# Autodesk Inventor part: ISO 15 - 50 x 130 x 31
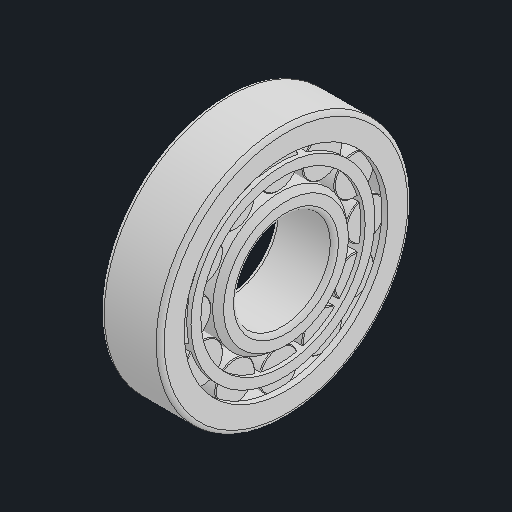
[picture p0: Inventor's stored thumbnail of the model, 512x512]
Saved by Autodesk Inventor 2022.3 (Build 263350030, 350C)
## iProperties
Created: 2020-09
Part Number: ISO 15 - 50 x 130 x 31
Material: Типовые
Document SubType Name: Modeling
Designer: Карташов
Density: 1 g/cm^3
Appearance: По умолчанию
Title: D:\мои документы\Ирина\_WorldSkills\2020_09 ФНЧ\Module A\GIVEN\ISO 15 - 50 x 130 x 31.stp
Author: Дом
Sending System: Autodesk Inventor 2021
Preprocessor: ST-DEVELOPER v18.1
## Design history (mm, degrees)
feature "Твердое тело2"
node "Твердое тело1"
